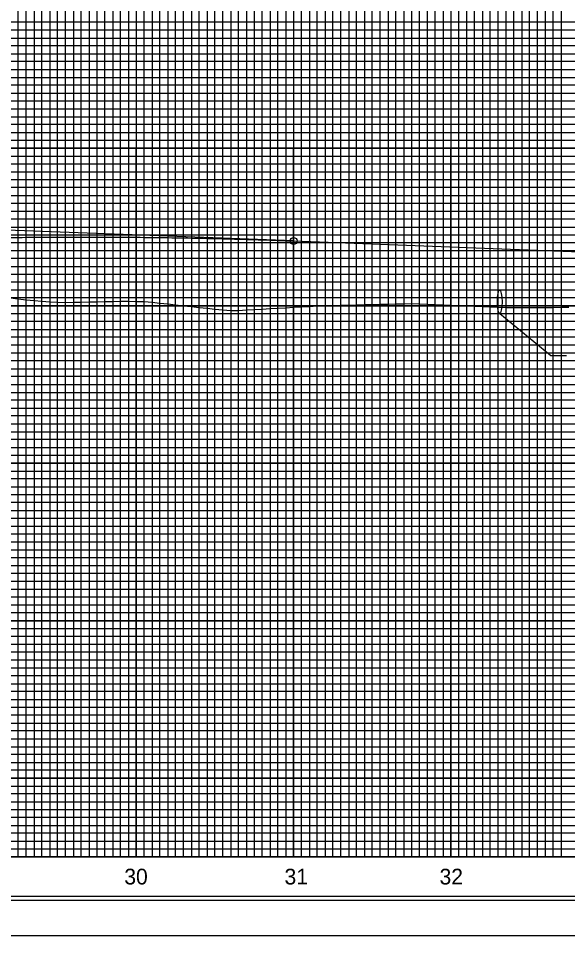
# Model space of a CAD drawing. Extents: x 2345490 to 2436403, y 465165 to 573888.
# Drawn here: x 2383692 to 2384041, y 500558 to 501140 of the extents above; entities that cross this region are included whole.
import ezdxf

# ---------------------------------------------------------------- set-up
doc = ezdxf.new("R2010")
doc.units = 0
for name, color, linetype in [('Exist Vertical Profile Horizontal Axis Label Major', 7, 'Continuous'), ('Old_Level_1', 7, 'Continuous'), ('Old_Level_18', 7, 'Continuous'), ('Old_Level_2', 7, 'Continuous'), ('Old_Level_3', 7, 'Continuous'), ('Old_Level_41', 7, 'Continuous'), ('Old_Level_42', 7, 'Continuous'), ('Old_Level_43', 7, 'Continuous'), ('Old_Level_50', 7, 'Continuous'), ('Old_Level_51', 7, 'Continuous'), ('Old_Level_57', 7, 'Continuous'), ('Old_Level_63', 7, 'Continuous')]:
    doc.layers.add(name, color=color, linetype=linetype)

msp = doc.modelspace()

# ---------------------------------------------------------------- linework, layer by layer
at = {"layer": 'Old_Level_1'}
for points in [[(2383686.7988, 500962.81258), (2383691.7988, 500962.21922), (2383696.7988, 500961.62585), (2383701.7988, 500961.06595), (2383706.7988, 500960.69882), (2383711.7988, 500960.33169), (2383716.7988, 500959.96456), (2383721.7988, 500959.90953), (2383726.7988, 500960.0128), (2383731.7988, 500960.11607), (2383736.7988, 500960.21934), (2383741.7988, 500960.32262), (2383746.7988, 500960.42589), (2383751.7988, 500960.52916), (2383756.7988, 500960.63243), (2383761.7988, 500960.69431), (2383766.7988, 500960.57193)], [(2383766.7988, 500960.57193), (2383771.7988, 500960.44956), (2383776.7988, 500960.04997), (2383781.7988, 500959.49163), (2383786.7988, 500958.93328), (2383791.7988, 500958.37493), (2383796.7988, 500957.81659), (2383801.7988, 500957.25824), (2383806.7988, 500956.69989), (2383811.7988, 500956.14155), (2383816.7988, 500955.5832), (2383821.7988, 500955.08817), (2383826.7988, 500954.80381), (2383831.7988, 500954.85618), (2383836.7988, 500955.12998), (2383841.7988, 500955.40379), (2383846.7988, 500955.67759), (2383851.7988, 500955.9514), (2383856.7988, 500956.2252), (2383861.7988, 500956.49901), (2383866.7988, 500956.77281), (2383871.7988, 500957.04661), (2383876.7988, 500957.32042), (2383881.7988, 500957.61659), (2383886.7988, 500957.84129), (2383891.7988, 500957.96852), (2383896.7988, 500958.09575), (2383901.7988, 500958.22298), (2383906.7988, 500958.35021), (2383911.7988, 500958.47744), (2383916.7988, 500958.60468), (2383921.7988, 500958.73191), (2383926.7988, 500958.85721), (2383931.7988, 500958.96428), (2383936.7988, 500959.07135), (2383941.7988, 500959.11939), (2383946.7988, 500958.91872), (2383951.7988, 500958.71804), (2383956.7988, 500958.51737), (2383961.7988, 500958.31669), (2383966.7988, 500958.11602), (2383971.7988, 500957.91535), (2383976.7988, 500957.71467), (2383981.7988, 500957.514), (2383986.7988, 500957.31332), (2383991.7988, 500957.11265), (2383996.7988, 500956.81529), (2384001.7988, 500956.579), (2384006.7988, 500956.60596), (2384011.7988, 500956.63292), (2384016.7988, 500956.65987), (2384021.7988, 500956.68683), (2384026.7988, 500956.71379), (2384031.7988, 500956.74075), (2384036.7988, 500956.76771), (2384041.7988, 500956.79467)]]:
    msp.add_lwpolyline(points, dxfattribs=at)
at = {"layer": 'Old_Level_18'}
msp.add_lwpolyline([(2384616.79875, 501632.775), (2383116.79875, 501632.775), (2383116.79875, 500582.775), (2384616.79875, 500582.775)], close=True, dxfattribs=at)
at = {"layer": 'Old_Level_2'}
for q in [(2383369.54725, 501017.6715), (2384326.799, 500981.54875)]:
    msp.add_line((2383866.799, 500998.90725), q, dxfattribs=at)
msp.add_circle((2383866.799, 500998.90725), 2.25, dxfattribs=at)
msp.add_spline([(2382866.799, 500894.56075), (2382886.799, 500899.4325), (2382906.799, 500904.19075), (2382926.799, 500908.835), (2382946.799, 500913.36575), (2382966.799, 500917.78275), (2382986.799, 500922.08625), (2383006.799, 500926.276), (2383026.799, 500930.352), (2383046.799, 500934.3145), (2383066.799, 500938.16325), (2383086.799, 500941.89825), (2383106.799, 500945.51975), (2383126.799, 500949.0275), (2383146.799, 500952.4215), (2383166.799, 500955.702), (2383186.799, 500958.86875), (2383206.799, 500961.92175), (2383226.799, 500964.86125), (2383246.799, 500967.687), (2383266.799, 500970.399), (2383286.799, 500972.9975), (2383306.799, 500975.48225), (2383326.799, 500977.8535), (2383346.799, 500980.11075), (2383366.799, 500982.2545), (2383386.799, 500984.28475), (2383406.799, 500986.201), (2383426.799, 500988.00375), (2383446.799, 500989.693), (2383466.799, 500991.2685), (2383486.799, 500992.73025), (2383506.799, 500994.07825), (2383526.799, 500995.31275), (2383546.799, 500996.4335), (2383566.799, 500997.4405), (2383586.799, 500998.334), (2383606.799, 500999.11375), (2383626.799, 500999.77975), (2383646.799, 501000.33225), (2383666.799, 501000.771), (2383686.799, 501001.09625), (2383706.799, 501001.30775), (2383726.799, 501001.4055), (2383746.799, 501001.3895), (2383766.799, 501001.26), (2383786.799, 501001.01675), (2383806.799, 501000.65975), (2383826.799, 501000.18925), (2383846.799, 500999.605), (2383866.799, 500998.90725)], degree=3, dxfattribs=at)
at = {"layer": 'Old_Level_3'}
msp.add_lwpolyline([(2383997.799, 500952.775), (2384030.22675, 500926.19), (2384040.22675, 500926.19)], dxfattribs=at)
msp.add_ellipse((2383997.799, 500960.275), major_axis=(0, 7.5), ratio=0.195724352, dxfattribs=at)
at = {"layer": 'Old_Level_41'}
msp.add_line((2384616.79875, 500607.775), (2383116.79875, 500607.775), dxfattribs=at)
for points in [[(2383641.79875, 500607.775), (2383691.79875, 500607.775), (2383691.79875, 501632.775)], [(2383666.79875, 500607.775), (2383716.79875, 500607.775), (2383716.79875, 501632.775)], [(2383741.79875, 501632.775), (2383741.79875, 500607.775), (2383791.79875, 500607.775), (2383791.79875, 501632.775)], [(2383766.79875, 501632.775), (2383766.79875, 500607.775), (2383816.79875, 500607.775), (2383816.79875, 501632.775)], [(2383841.79875, 501632.775), (2383841.79875, 500607.775), (2383891.79875, 500607.775), (2383891.79875, 501632.775)], [(2383866.79875, 501632.775), (2383866.79875, 500607.775), (2383916.79875, 500607.775), (2383916.79875, 501632.775)], [(2383941.79875, 501632.775), (2383941.79875, 500607.775), (2383991.79875, 500607.775), (2383991.79875, 501632.775)], [(2383966.79875, 501632.775), (2383966.79875, 500607.775), (2384016.79875, 500607.775), (2384016.79875, 501632.775)], [(2384616.79875, 501132.775), (2383116.79875, 501132.775), (2383116.79875, 501082.775), (2384616.79875, 501082.775)], [(2384616.79875, 501032.775), (2383116.79875, 501032.775), (2383116.79875, 500982.775), (2384616.79875, 500982.775)], [(2384616.79875, 500957.775), (2383116.79875, 500957.775), (2383116.79875, 501007.775), (2384616.79875, 501007.775)], [(2384616.79875, 500932.775), (2383116.79875, 500932.775), (2383116.79875, 500882.775), (2384616.79875, 500882.775)], [(2384616.79875, 500857.775), (2383116.79875, 500857.775), (2383116.79875, 500907.775), (2384616.79875, 500907.775)], [(2384616.79875, 500832.775), (2383116.79875, 500832.775), (2383116.79875, 500782.775), (2384616.79875, 500782.775)], [(2384616.79875, 500732.775), (2383116.79875, 500732.775), (2383116.79875, 500682.775), (2384616.79875, 500682.775)], [(2384616.79875, 500657.775), (2383116.79875, 500657.775), (2383116.79875, 500707.775), (2384616.79875, 500707.775)], [(2384616.79875, 500632.775), (2383116.79875, 500632.775)]]:
    msp.add_lwpolyline(points, dxfattribs=at)
at = {"layer": 'Old_Level_42'}
for points in [[(2384616.79875, 501057.775), (2383116.79875, 501057.775), (2383116.79875, 501107.775), (2384616.79875, 501107.775)], [(2384616.79875, 500757.775), (2383116.79875, 500757.775), (2383116.79875, 500807.775), (2384616.79875, 500807.775)]]:
    msp.add_lwpolyline(points, dxfattribs=at)
at = {"layer": 'Old_Level_43'}
for points in [[(2383696.79875, 500607.775), (2383696.79875, 501632.775)], [(2383701.79875, 501632.775), (2383701.79875, 500607.775), (2383706.79875, 500607.775), (2383706.79875, 501632.775)], [(2383711.79875, 501632.775), (2383711.79875, 500607.775), (2383721.79875, 500607.775), (2383721.79875, 501632.775)], [(2383726.79875, 501632.775), (2383726.79875, 500607.775), (2383726.79875, 500607.775), (2383731.79875, 500607.775), (2383731.79875, 501632.775)], [(2383736.79875, 501632.775), (2383736.79875, 500607.775), (2383746.79875, 500607.775), (2383746.79875, 501632.775)], [(2383751.79875, 501632.775), (2383751.79875, 500607.775), (2383756.79875, 500607.775), (2383756.79875, 501632.775)], [(2383761.79875, 501632.775), (2383761.79875, 500607.775), (2383771.79875, 500607.775), (2383771.79875, 501632.775)], [(2383776.79875, 501632.775), (2383776.79875, 500607.775), (2383781.79875, 500607.775), (2383781.79875, 501632.775)], [(2383786.79875, 501632.775), (2383786.79875, 500607.775), (2383796.79875, 500607.775), (2383796.79875, 501632.775)], [(2383801.79875, 501632.775), (2383801.79875, 500607.775), (2383806.79875, 500607.775), (2383806.79875, 501632.775)], [(2383811.79875, 501632.775), (2383811.79875, 500607.775), (2383821.79875, 500607.775), (2383821.79875, 501632.775)], [(2383826.79875, 501632.775), (2383826.79875, 500607.775), (2383831.79875, 500607.775), (2383831.79875, 501632.775)], [(2383836.79875, 501632.775), (2383836.79875, 500607.775), (2383846.79875, 500607.775), (2383846.79875, 501632.775)], [(2383851.79875, 501632.775), (2383851.79875, 500607.775), (2383856.79875, 500607.775), (2383856.79875, 501632.775)], [(2383861.79875, 501632.775), (2383861.79875, 500607.775), (2383871.79875, 500607.775), (2383871.79875, 501632.775)], [(2383876.79875, 501632.775), (2383876.79875, 500607.775)], [(2383876.79875, 500607.775), (2383881.79875, 500607.775), (2383881.79875, 501632.175)], [(2383886.79875, 501632.175), (2383886.79875, 500607.775), (2383896.79875, 500607.775), (2383896.79875, 501632.775)], [(2383901.79875, 501632.775), (2383901.79875, 500607.775), (2383906.79875, 500607.775), (2383906.79875, 501632.775)], [(2383911.79875, 501632.775), (2383911.79875, 500607.775), (2383921.79875, 500607.775), (2383921.79875, 501632.775)], [(2383926.79875, 501632.775), (2383926.79875, 500607.775), (2383931.79875, 500607.775), (2383931.79875, 501632.775)], [(2383936.79875, 501632.775), (2383936.79875, 500607.775), (2383946.79875, 500607.775), (2383946.79875, 501632.775)], [(2383951.79875, 501632.775), (2383951.79875, 500607.775), (2383956.79875, 500607.775), (2383956.79875, 501632.775)], [(2383961.79875, 501632.775), (2383961.79875, 500607.775), (2383971.79875, 500607.775), (2383971.79875, 501632.775)], [(2383976.79875, 501632.775), (2383976.79875, 500607.775), (2383981.79875, 500607.775), (2383981.79875, 501632.775)], [(2383986.79875, 501632.775), (2383986.79875, 500607.775), (2383996.79875, 500607.775), (2383996.79875, 501632.775)], [(2384001.79875, 501632.775), (2384001.79875, 500607.775), (2384006.79875, 500607.775), (2384006.79875, 501632.775)], [(2384011.79875, 501632.775), (2384011.79875, 500607.775), (2384021.79875, 500607.775), (2384021.79875, 501632.775)], [(2384026.79875, 501632.775), (2384026.79875, 500607.775), (2384031.79875, 500607.775), (2384031.79875, 501632.775)], [(2384036.79875, 501632.775), (2384036.79875, 500607.775), (2384046.79875, 500607.775), (2384046.79875, 501632.775)], [(2384566.79875, 501137.775), (2383166.79875, 501137.775), (2383166.79875, 501127.775), (2384566.79875, 501127.775)], [(2384566.79875, 501122.775), (2383166.79875, 501122.775), (2383166.79875, 501117.775), (2384566.79875, 501117.775)], [(2384566.79875, 501112.775), (2383166.79875, 501112.775)], [(2383166.79875, 501102.775), (2384566.79875, 501102.775)], [(2384566.79875, 501097.775), (2383166.79875, 501097.775), (2383166.79875, 501092.775), (2384566.79875, 501092.775)], [(2384566.79875, 501087.775), (2383166.79875, 501087.775), (2383166.79875, 501077.775), (2384566.79875, 501077.775)], [(2384566.79875, 501072.775), (2383166.79875, 501072.775), (2383166.79875, 501067.775), (2384566.79875, 501067.775)], [(2384566.79875, 501062.775), (2383166.79875, 501062.775), (2383166.79875, 501052.775), (2384566.79875, 501052.775)], [(2384566.79875, 501047.775), (2383166.79875, 501047.775), (2383166.79875, 501042.775), (2384566.79875, 501042.775)], [(2384566.79875, 501037.775), (2383166.79875, 501037.775), (2383166.79875, 501027.775), (2384566.79875, 501027.775)], [(2384566.79875, 501022.775), (2383166.79875, 501022.775), (2383166.79875, 501017.775), (2384566.79875, 501017.775)], [(2384566.79875, 501012.775), (2383166.79875, 501012.775), (2383166.79875, 501002.775), (2384566.79875, 501002.775)], [(2384566.79875, 500997.775), (2383166.79875, 500997.775), (2383166.79875, 500992.775), (2384566.79875, 500992.775)], [(2384566.79875, 500987.775), (2383166.79875, 500987.775), (2383166.79875, 500977.775), (2384566.79875, 500977.775)], [(2384566.79875, 500972.775), (2383166.79875, 500972.775), (2383166.79875, 500967.775), (2384566.79875, 500967.775)], [(2384566.79875, 500962.775), (2383166.79875, 500962.775), (2383166.79875, 500952.775), (2384566.79875, 500952.775)], [(2384566.79875, 500947.775), (2383166.79875, 500947.775), (2383166.79875, 500942.775), (2384566.79875, 500942.775)], [(2384566.79875, 500937.775), (2383166.79875, 500937.775), (2383166.79875, 500927.775), (2384566.79875, 500927.775)], [(2384566.79875, 500922.775), (2383166.79875, 500922.775), (2383166.79875, 500917.775), (2384566.79875, 500917.775)], [(2384566.79875, 500912.775), (2383166.79875, 500912.775), (2383166.79875, 500902.775), (2384566.79875, 500902.775)], [(2384566.79875, 500897.775), (2383166.79875, 500897.775), (2383166.79875, 500892.775), (2384566.79875, 500892.775)], [(2384566.79875, 500887.775), (2383166.79875, 500887.775), (2383166.79875, 500877.775), (2384566.79875, 500877.775)], [(2384566.79875, 500872.775), (2383166.79875, 500872.775), (2383166.79875, 500867.775), (2384566.79875, 500867.775)], [(2384566.79875, 500862.775), (2383166.79875, 500862.775), (2383166.79875, 500852.775), (2384566.79875, 500852.775)], [(2384566.79875, 500847.775), (2383166.79875, 500847.775), (2383166.79875, 500842.775), (2384566.79875, 500842.775)], [(2384566.79875, 500837.775), (2383166.79875, 500837.775), (2383166.79875, 500827.775), (2384566.79875, 500827.775)], [(2384566.79875, 500822.775), (2383166.79875, 500822.775), (2383166.79875, 500817.775), (2384566.79875, 500817.775)], [(2384566.79875, 500812.775), (2383166.79875, 500812.775)], [(2383166.79875, 500802.775), (2384566.79875, 500802.775)], [(2384566.79875, 500797.775), (2383166.79875, 500797.775), (2383166.79875, 500792.775), (2384566.79875, 500792.775)], [(2384566.79875, 500787.775), (2383166.79875, 500787.775)], [(2383166.79875, 500777.775), (2384566.79875, 500777.775)], [(2384566.79875, 500772.775), (2383166.79875, 500772.775), (2383166.79875, 500767.775), (2384566.79875, 500767.775)], [(2384566.79875, 500762.775), (2383166.79875, 500762.775), (2383166.79875, 500752.775), (2384566.79875, 500752.775)], [(2384566.79875, 500747.775), (2383166.79875, 500747.775), (2383166.79875, 500742.775), (2384566.79875, 500742.775)], [(2384566.79875, 500737.775), (2383166.79875, 500737.775), (2383166.79875, 500727.775), (2384566.79875, 500727.775)], [(2384566.79875, 500722.775), (2383166.79875, 500722.775), (2383166.79875, 500717.775), (2384566.79875, 500717.775)], [(2384566.79875, 500712.775), (2383166.79875, 500712.775), (2383166.79875, 500702.775), (2384566.79875, 500702.775)], [(2384566.79875, 500697.775), (2383166.79875, 500697.775), (2383166.79875, 500692.775), (2384566.79875, 500692.775)], [(2384566.79875, 500687.775), (2383166.79875, 500687.775), (2383166.79875, 500677.775), (2384566.79875, 500677.775)], [(2384566.79875, 500672.775), (2383166.79875, 500672.775), (2383166.79875, 500667.775), (2384566.79875, 500667.775)], [(2384566.79875, 500662.775), (2383166.79875, 500662.775), (2383166.79875, 500652.775), (2384566.79875, 500652.775)], [(2384566.79875, 500647.775), (2383166.79875, 500647.775), (2383166.79875, 500642.775), (2384566.79875, 500642.775)], [(2384566.79875, 500637.775), (2383166.79875, 500637.775), (2383166.79875, 500627.775), (2384566.79875, 500627.775)], [(2384566.79875, 500622.775), (2383166.79875, 500622.775), (2383166.79875, 500617.775), (2384566.79875, 500617.775)], [(2384566.79875, 500612.775), (2383166.79875, 500612.775)]]:
    msp.add_lwpolyline(points, dxfattribs=at)
at = {"layer": 'Old_Level_50'}
msp.add_lwpolyline([(2384629.29875, 501635.325), (2382962.79875, 501635.325), (2382962.79875, 500580.225), (2384629.29875, 500580.225)], close=True, dxfattribs=at)
at = {"layer": 'Old_Level_51'}
msp.add_lwpolyline([(2384633.79875, 501657.775), (2382949.79875, 501657.775), (2382949.79875, 500557.775), (2384633.79875, 500557.775)], close=True, dxfattribs=at)
at = {"layer": 'Old_Level_57'}
for p, q in [((2381716.79925, 501057.77525), (2385066.79875, 501057.77525)), ((2383766.79875, 500607.77525), (2383766.79875, 501057.77525)), ((2383766.79875, 500607.87525), (2383766.79875, 501057.77525)), ((2383866.79875, 500607.77525), (2383866.79875, 501057.77525)), ((2383866.79875, 500607.87525), (2383866.79875, 501057.77525)), ((2383966.79875, 500607.77525), (2383966.79875, 501057.77525)), ((2383966.79875, 500607.87525), (2383966.79875, 501057.77525)), ((2381716.79925, 501007.77525), (2385066.79875, 501007.77525)), ((2381716.79925, 500957.77525), (2385066.79875, 500957.77525)), ((2381716.79925, 500907.77525), (2385066.79875, 500907.77525)), ((2381716.79925, 500857.77525), (2385066.79875, 500857.77525)), ((2381716.79925, 500807.77525), (2385066.79875, 500807.77525)), ((2381716.79925, 500757.77525), (2385066.79875, 500757.77525)), ((2381716.79925, 500707.77525), (2385066.79875, 500707.77525)), ((2381716.799, 500657.77525), (2385066.79875, 500657.77525)), ((2381716.79925, 500607.77525), (2385066.79875, 500607.77525))]:
    msp.add_line(p, q, dxfattribs=at)
at = {"layer": 'Old_Level_63'}
msp.add_line((2381766.79875, 500607.775), (2384797.7405, 500607.775), dxfattribs=at)

# ---------------------------------------------------------------- texts
at = {"layer": 'Exist Vertical Profile Horizontal Axis Label Major'}
for s, p in [('30', (2383759.18516, 500590.275)), ('31', (2383861.02456, 500590.275)), ('32', (2383959.57304, 500590.275))]:
    msp.add_text(s, height=10, dxfattribs=at).set_placement(p)

doc.saveas('drawing.dxf')
